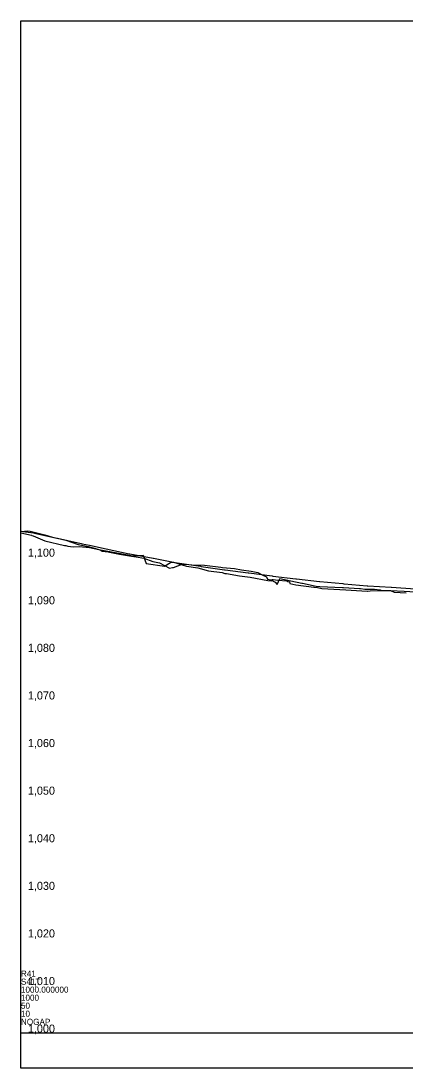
# Model space of a CAD drawing. Extents: x 1545155 to 1547500, y 1196198 to 1197298.
# Drawn here: x 1545155 to 1545559, y 1196198 to 1197298 of the extents above; entities that cross this region are included whole.
import ezdxf

# ---------------------------------------------------------------- set-up
doc = ezdxf.new("R2010")
doc.units = 0
for name, color, linetype in [('BR_CONCRETE', 7, 'Continuous'), ('BR_PROPOSED_TRAVELWAY', 7, 'Continuous'), ('RD_PD_ALT1_TX', 7, 'Continuous'), ('RD_PD_CstnLmt_TX', 7, 'Continuous'), ('RD_PD_RW_TX', 7, 'Continuous'), ('RD_Sketch2', 7, 'Continuous')]:
    doc.layers.add(name, color=color, linetype=linetype)

msp = doc.modelspace()

# ---------------------------------------------------------------- linework, layer by layer
at = {"layer": 'BR_CONCRETE'}
msp.add_lwpolyline([(1545155, 1196762.2), (1545155.7, 1196762.2), (1545156.9, 1196762), (1545168.2, 1196760.4), (1545169.2, 1196760), (1545192.8, 1196754.9), (1545193.3, 1196754.8), (1545218.2, 1196749.4), (1545219.5, 1196749.1), (1545227.2, 1196747.5), (1545244.4, 1196743.7), (1545268.6, 1196738.5), (1545268.9, 1196738.4), (1545269.4, 1196738.3), (1545293.9, 1196733.7), (1545294.3, 1196733.7), (1545318.8, 1196729.1), (1545319.3, 1196729), (1545343.8, 1196725.3), (1545344.5, 1196725.2), (1545368.8, 1196721.6), (1545369.7, 1196721.5), (1545393.8, 1196718.4), (1545394.6, 1196718.3), (1545418.9, 1196715.2), (1545419.8, 1196715.1), (1545443.7, 1196712.3), (1545444.7, 1196712.2), (1545468.7, 1196709.3), (1545469.2, 1196709.3), (1545493.3, 1196707.1), (1545494.2, 1196707), (1545494.7, 1196707), (1545518.9, 1196704.8), (1545519.6, 1196704.8), (1545543.9, 1196703.3), (1545544.4, 1196703.3), (1545569.2, 1196701.7)], dxfattribs=at)
at = {"layer": 'BR_PROPOSED_TRAVELWAY'}
msp.add_lwpolyline([(1545155, 1197298.2), (1546955, 1197298.2), (1546955, 1196198.2), (1545155, 1196198.2)], close=True, dxfattribs=at)
at = {"layer": 'RD_PD_ALT1_TX'}
msp.add_lwpolyline([(1545155, 1196760.6), (1545166.1, 1196757.9), (1545166.5, 1196757.8), (1545167.8, 1196757.4), (1545180.1, 1196752), (1545200.7, 1196747.3), (1545202, 1196747), (1545204.3, 1196746.5), (1545210, 1196745.9), (1545216.1, 1196746.2), (1545226.9, 1196744.9), (1545236.8, 1196742.8), (1545244.7, 1196741.6), (1545267.1, 1196737.5), (1545270.5, 1196736.8), (1545272.5, 1196736.4), (1545279.1, 1196736.5), (1545283.6, 1196737), (1545286.6, 1196728.3), (1545306, 1196725.6), (1545312, 1196729.3), (1545312.7, 1196729.8), (1545315.2, 1196729.5), (1545328.8, 1196725.4), (1545340.9, 1196723.7), (1545352.1, 1196720.7), (1545366.3, 1196718.7), (1545369.3, 1196717.9), (1545371.1, 1196717.7), (1545384.7, 1196715.4), (1545395.8, 1196713.9), (1545414.5, 1196710.5), (1545418.5, 1196710), (1545418.8, 1196711.3), (1545420.1, 1196711.4), (1545424.9, 1196710.9), (1545434.5, 1196710.1), (1545435.4, 1196709.5), (1545437.2, 1196709.1), (1545437.7, 1196707.2), (1545443.8, 1196705.9), (1545462.8, 1196703.4), (1545463.1, 1196703.3), (1545466.5, 1196702.9), (1545471.2, 1196701.9), (1545496.3, 1196700.5), (1545518.8, 1196699.2), (1545519.2, 1196699.3), (1545522.1, 1196699.6), (1545543.4, 1196699.8), (1545547.1, 1196698.3), (1545559.8, 1196697.6)], dxfattribs=at)
at = {"layer": 'RD_PD_RW_TX'}
msp.add_lwpolyline([(1545155, 1196762), (1545158.6, 1196762.4), (1545161.8, 1196762.7), (1545164.7, 1196762.3), (1545180, 1196758.4), (1545188, 1196756.1), (1545192.9, 1196754.9), (1545202.3, 1196752.7), (1545215.3, 1196748.3), (1545225.7, 1196746.1), (1545229.4, 1196745.1), (1545238.3, 1196742.5), (1545240.5, 1196741.2), (1545243.4, 1196741), (1545244.9, 1196740.8), (1545249.9, 1196739.7), (1545258.7, 1196738), (1545271.2, 1196736.1), (1545276.1, 1196735.4), (1545284.2, 1196733.9), (1545293.6, 1196730.3), (1545300.7, 1196728.8), (1545311.2, 1196723.5), (1545314.3, 1196723.9), (1545315.2, 1196724.1), (1545324.5, 1196727.7), (1545325.9, 1196727.5), (1545328.2, 1196727.4), (1545334.5, 1196726.7), (1545347.7, 1196726.6), (1545364.9, 1196724.3), (1545366.7, 1196724.1), (1545379.5, 1196723), (1545386.9, 1196721.7), (1545397, 1196720.3), (1545403.8, 1196718.7), (1545409.3, 1196716.1), (1545413, 1196714.1), (1545413.9, 1196711.9), (1545417.5, 1196711.1), (1545422.1, 1196708.7), (1545424.4, 1196706.2), (1545427.1, 1196712.5), (1545450.1, 1196707.7), (1545450.7, 1196707.6), (1545465.2, 1196704.6), (1545468.9, 1196704), (1545492.8, 1196702.9), (1545493.9, 1196702.9), (1545510.7, 1196702.1), (1545511.8, 1196701.9), (1545516.3, 1196701.4), (1545526.6, 1196701.4), (1545532.6, 1196700.6), (1545533.3, 1196700.3), (1545543.3, 1196700), (1545557.7, 1196699.3), (1545575.5, 1196698.3)], dxfattribs=at)
at = {"layer": 'RD_Sketch2'}
for q in [(1545155, 1196485.2), (1547500.4, 1196235.2), (1545155, 1196235.2)]:
    msp.add_line((1545155, 1196235.2), q, dxfattribs=at)

# ---------------------------------------------------------------- texts
at = {"layer": 'RD_PD_CstnLmt_TX'}
for s, p in [('1,100', (1545162.3, 1196735.4)), ('1,090', (1545162.3, 1196685.4)), ('1,080', (1545162.3, 1196635.4)), ('1,070', (1545162.3, 1196585.4)), ('1,060', (1545162.3, 1196535.4)), ('1,050', (1545162.3, 1196485.4)), ('1,040', (1545162.3, 1196435.4)), ('1,030', (1545162.3, 1196385.4)), ('1,020', (1545162.3, 1196335.4)), ('1,010', (1545162.3, 1196285.4)), ('1,000', (1545162.3, 1196235.4))]:
    msp.add_text(s, height=8.5, dxfattribs=at).set_placement(p)
at = {"layer": 'RD_Sketch2'}
for s, p in [('R41', (1545155, 1196294.3)), ('S41T', (1545155, 1196285.8)), ('1000.000000', (1545155, 1196277.4)), ('1000', (1545155, 1196268.9)), ('50', (1545155, 1196260.5)), ('10', (1545155, 1196252.1)), ('NOGAP', (1545155, 1196243.6))]:
    msp.add_text(s, height=6.4, dxfattribs=at).set_placement(p)

doc.saveas('drawing.dxf')
